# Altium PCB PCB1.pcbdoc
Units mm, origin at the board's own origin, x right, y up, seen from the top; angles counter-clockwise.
Board outline 74.17 x 55.75 mm, 2 copper layers (Top Layer, Bottom Layer); 37 components, 49 nets, 196 pads, 123 vias.
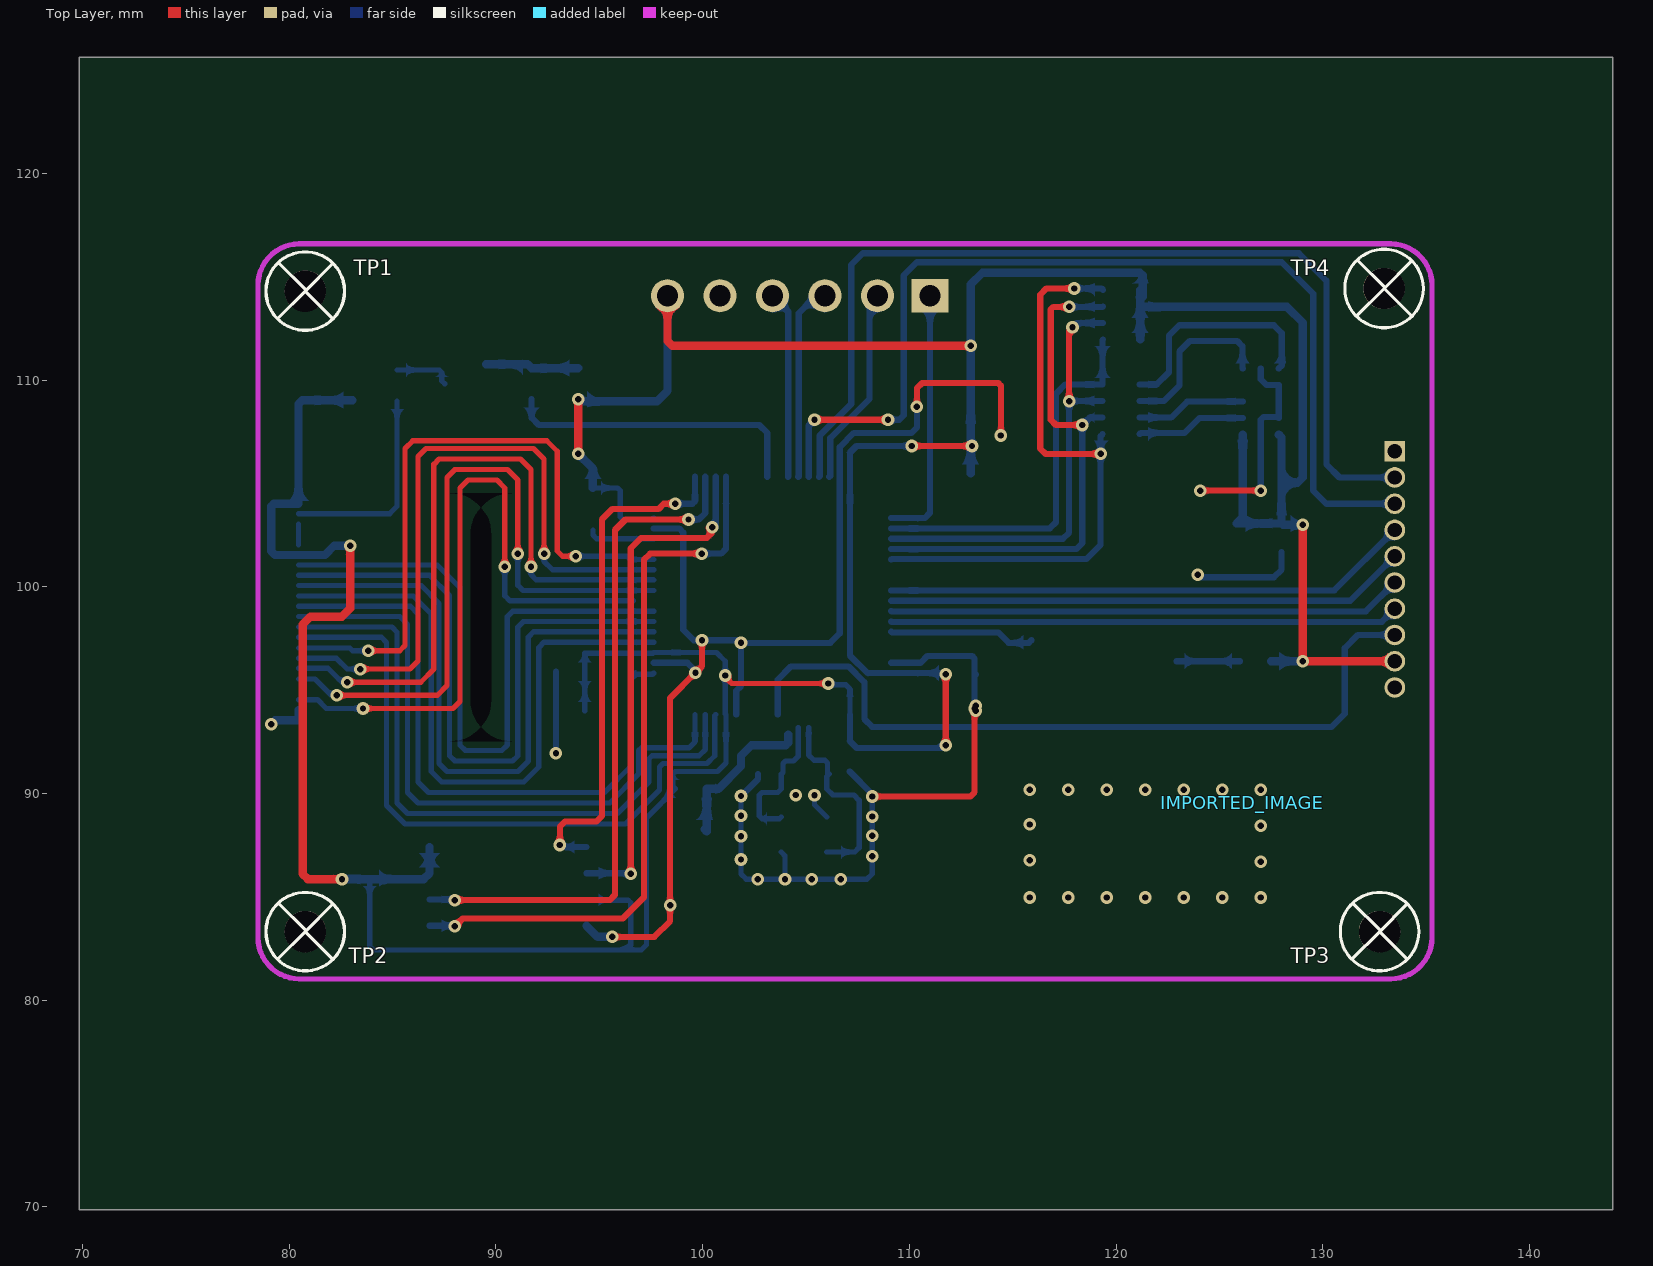
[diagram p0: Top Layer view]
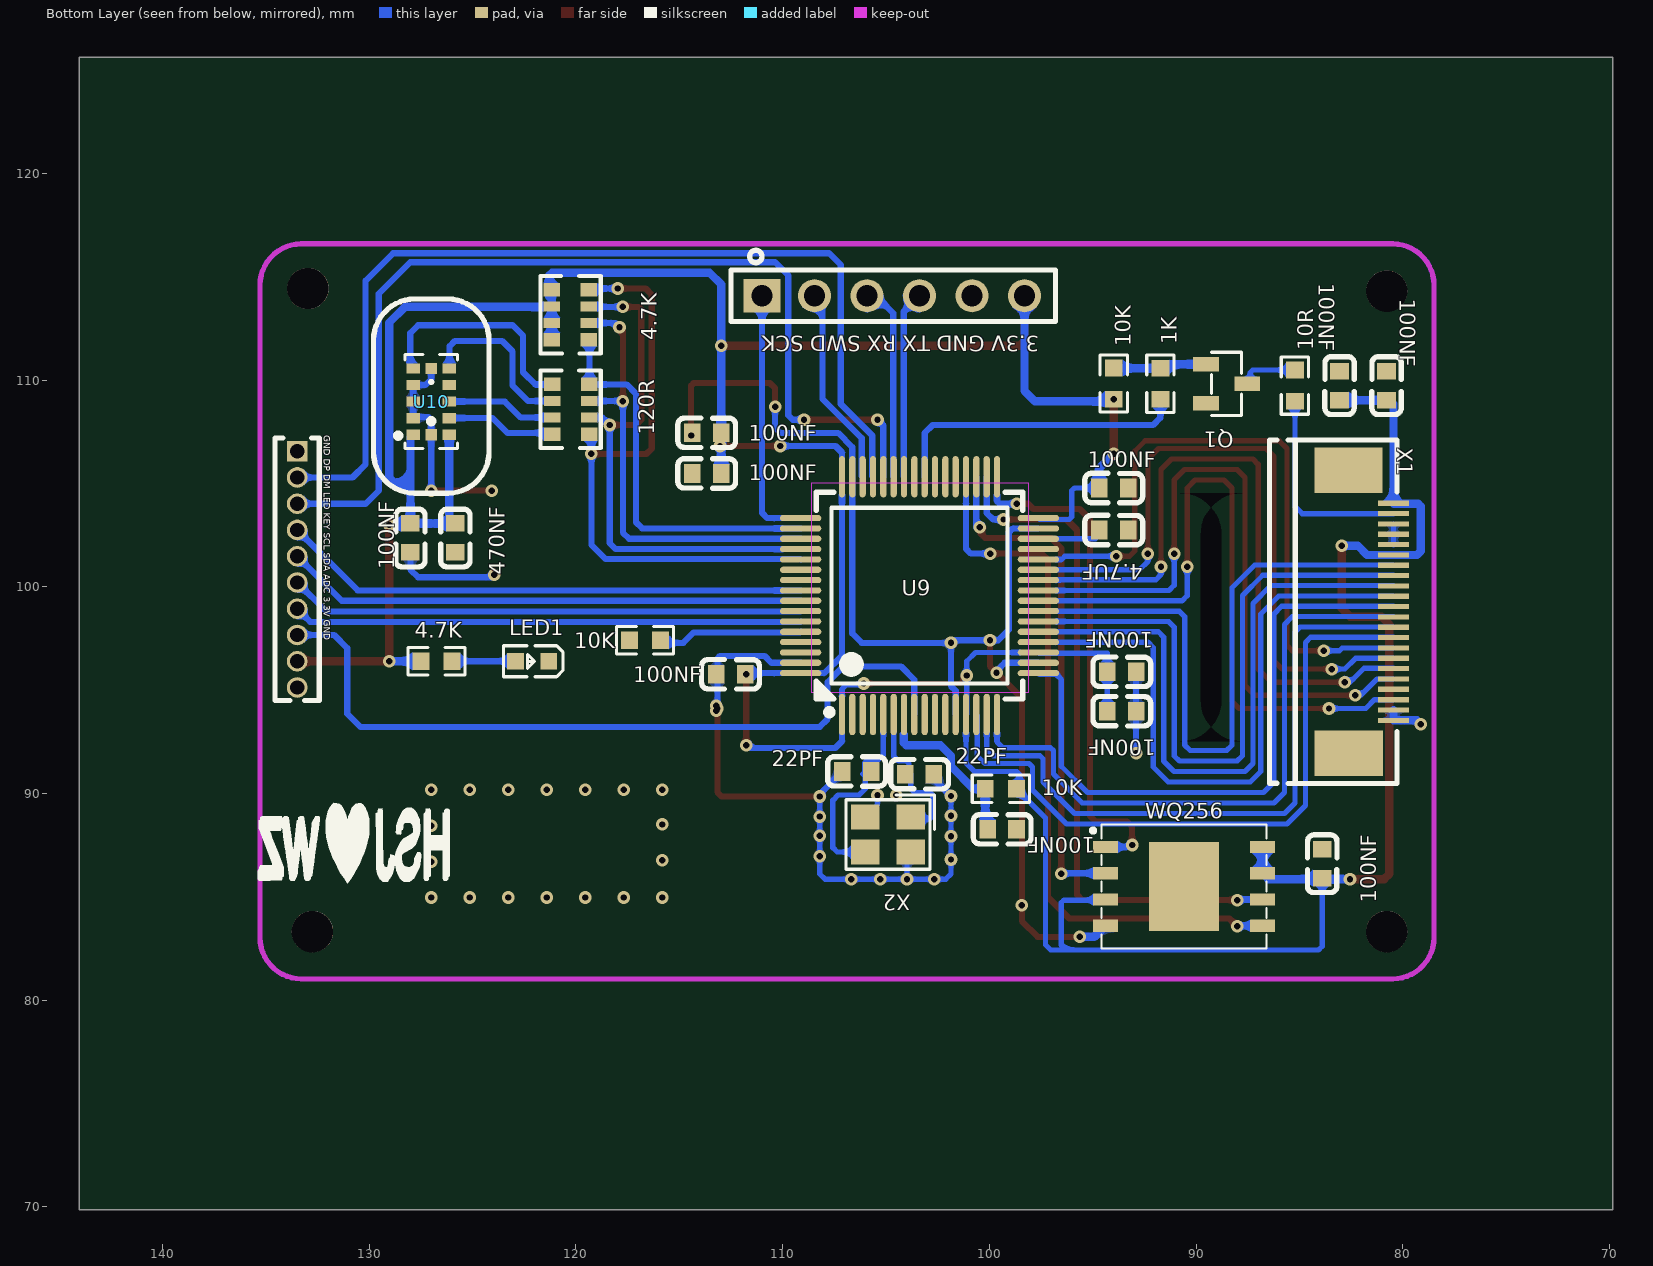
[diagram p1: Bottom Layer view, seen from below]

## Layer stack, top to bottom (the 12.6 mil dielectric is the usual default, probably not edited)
Top Layer: signal copper (thickness not stored)
Dielectric: dielectric 0.32, FR-4, Dk 4.8
Bottom Layer: signal copper (thickness not stored)

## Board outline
144.018,69.85 69.85,69.85 69.85,125.603 144.018,125.603
cut-out: 90.773,104.521 87.773,104.521 cw(c87.773,102.521) 89.773,102.521 89.773,94.521 cw(c87.773,94.521) 87.773,92.521 90.773,92.521 cw(c90.773,94.521) 88.773,94.521 88.773,102.521 cw(c90.773,102.521)

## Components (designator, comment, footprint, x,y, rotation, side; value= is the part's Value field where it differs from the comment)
1K "Res_0603" R0603 91.723,109.818 r90 bottom
"3.3V GND TX RX SWD SCK" "HDR-F_2.54_1x6P" HDR-TH_6P-P2.54-V-F 104.648,114.076 r180 bottom
4.7K "Res_0603" R0603 126.746,96.393 r180 bottom
4.7K "4D03WGJ0103T5E" RES-ARRAY-SMD_0603-8P-L3.2-W1.6-BL 120.269,113.157 r90 top
4.7UF "CAP_0603" C0603 93.988,102.743 r0 bottom
10K "Res_0603" R0603 99.441,90.223 r0 bottom
10K "Res_0603" R0603 116.659,97.409 r0 bottom
10K "Res_0603" R0603 93.98,109.829 r90 bottom
10R "Res_0603" R0603 85.217,109.731 r90 bottom
22PF "CAP_0603" C0603 106.412,91.059 r180 bottom
22PF "CAP_0603" C0603 103.378,90.932 r0 bottom
100NF "CAP_0603" C0603 83.892,86.605 r90 bottom
100NF "CAP_0603" C0603 93.988,104.775 r0 bottom
100NF "CAP_0603" C0603 93.599,95.885 r0 bottom
100NF "CAP_0603" C0603 112.514,95.758 r180 bottom
100NF "CAP_0603" C0603 113.665,105.475 r180 bottom
100NF "CAP_0603" C0603 113.665,107.442 r180 bottom
100NF "CAP_0603" C0603 93.599,93.98 r0 bottom
100NF "CAP_0603" C0603 99.385,88.265 r0 bottom
100NF "CAP_0603" C0603 83.058,109.723 r270 bottom
100NF "CAP_0603" C0603 80.782,109.723 r270 bottom
100NF "CAP_0603" C0603 128.007,102.362 r90 bottom
120R "4D03WGJ0103T5E" RES-ARRAY-SMD_0603-8P-L3.2-W1.6-BL 120.249,108.585 r270 top
470NF "CAP_0603" C0603 125.83,102.362 r90 bottom
"GND DP DM LED KEY SCL SDA ADC 3.3V GND" "KH-1.27PH180-1X10P-L7.2" HDR-TH_10P-P1.27-V-M 133.486,100.838 r270 bottom
IMPORTED_IMAGE "IMPORTED_IMAGE" IMPORTED_IMAGE 126.111,89.535 r0 top
LED1 "LED_0603-R" LED_0603 122.174,96.39 r0 bottom
Q1 "SS8050_C2150" SOT-23-3_L2.9-W1.3-P1.90-LS2.4-BR 88.519,109.815 r0 bottom
TP1 "M2螺丝" M2螺丝 80.772,114.3 r0 top
TP2 "M2螺丝" M2螺丝 80.772,83.312 r0 top
TP3 "M2螺丝" M2螺丝 132.75,83.312 r0 top
TP4 "M2螺丝" M2螺丝 132.969,114.427 r0 top
U9 "STM32F446RET6" LQFP-64_L10.0-W10.0-P0.50-LS12.0-BL 103.378,99.568 r180 bottom
U10 "VL53L0CXV0DH/1" OPTO-SMD_12P_VL53L0CXV0DH-1 127,108.957 r270 bottom
WQ256 "W25Q256JVEIQ" WSON-8_L6.0-W8.0-P1.27-BL-EP 90.583,85.5 r270 bottom
X1 "AFC07-S22ECA-00" FPC-SMD_AFC07-S22ECA-00 81.534,98.784 r270 bottom
X2 "3225-8.00-12-10-10/A" CRYSTAL-SMD_4P-L3.2-W2.5-BL 104.902,88.011 r0 bottom

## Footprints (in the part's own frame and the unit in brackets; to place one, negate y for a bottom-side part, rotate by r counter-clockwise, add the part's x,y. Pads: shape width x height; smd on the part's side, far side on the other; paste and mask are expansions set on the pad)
C0603 [mm]
  rect 0.8x0.9 smd paste+0 mask+0.051: 1(-0.7,0) 2(0.7,0)
  silkscreen extent -1.41,-0.71 1.39,0.72
CRYSTAL-SMD_4P-L3.2-W2.5-BL [mm]
  rect 1.4x1.2 smd mask+0.051: 1(-1.1,-0.85) 2(1.1,-0.85) 3(1.1,0.85) 4(-1.1,0.85)
  silkscreen extent -2.26,-1.91 2.03,1.68
FPC-SMD_AFC07-S22ECA-00 [mm]
  rect 0.25x1.5 smd mask+0.051: 1(-5.25,1.085) 2(-4.75,1.085) 3(-4.25,1.085) 4(-3.75,1.085) 5(-3.25,1.085) 6(-2.75,1.085) 7(-2.25,1.085) 8(-1.75,1.085) 9(-1.25,1.085) 10(-0.75,1.085) 11(-0.25,1.085) 12(0.25,1.085) 13(0.75,1.085) 14(1.25,1.085) 15(1.75,1.085) 16(2.25,1.085) 17(2.75,1.085) 18(3.25,1.085) 19(3.75,1.085) 20(4.25,1.085) 21(4.75,1.085) 22(5.25,1.085)
  rect 2.2x3.3 smd mask+0.051: 23(6.85,-1.078) 24(-6.851,-1.085)
  silkscreen extent -8.31,-4.91 8.3,1.26
HDR-TH_6P-P2.54-V-F [mm]
  rect 1.8x1.6 hole 1.02 mask+0.051: 1(-6.35,0)
  round 1.6 hole 1.02 mask+0.051: 2(-3.81,0) 3(-1.27,0) 4(1.27,0) 5(3.81,0) 6(6.35,0)
  silkscreen extent -7.85,-1.25 7.85,2.2
HDR-TH_10P-P1.27-V-M [mm]
  rect 1x1 hole 0.7 mask+0.051: 1(-5.715,0)
  round 1 hole 0.7 mask+0.051: 2(-4.445,0) 3(-3.175,0) 4(-1.905,0) 5(-0.635,0) 6(0.635,0) 7(1.905,0) 8(3.175,0) 9(4.445,0) 10(5.715,0)
  silkscreen extent -6.35,-1.07 6.35,1.07
IMPORTED_IMAGE [mm]
LED_0603 [mil]
  rect 31.5x31.5 smd paste+0 mask+2: 1(-33.5,-0.4) 2(29.5,-0.2)
  silkscreen extent -61,-30 53,30
LQFP-64_L10.0-W10.0-P0.50-LS12.0-BL [mm]
  oval 0.3x2 smd paste+0 mask+0.051: 1(-3.75,-5.75) 2(-3.25,-5.75) 3(-2.75,-5.75) 4(-2.25,-5.75) 5(-1.75,-5.75) 6(-1.25,-5.75) 7(-0.75,-5.75) 8(-0.25,-5.75) 9(0.25,-5.75) 10(0.75,-5.75) 11(1.25,-5.75) 12(1.75,-5.75) 13(2.25,-5.75) 14(2.75,-5.75) 15(3.25,-5.75) 16(3.75,-5.75) 33(3.75,5.75) 34(3.25,5.75) 35(2.75,5.75) 36(2.25,5.75) 37(1.75,5.75) 38(1.25,5.75) 39(0.75,5.75) 40(0.25,5.75) 41(-0.25,5.75) 42(-0.75,5.75) 43(-1.25,5.75) 44(-1.75,5.75) 45(-2.25,5.75) 46(-2.75,5.75) 47(-3.25,5.75) 48(-3.75,5.75)
  oval 2x0.3 smd paste+0 mask+0.051: 17(5.75,-3.75) 18(5.75,-3.25) 19(5.75,-2.75) 20(5.75,-2.25) 21(5.75,-1.75) 22(5.75,-1.25) 23(5.75,-0.75) 24(5.75,-0.25) 25(5.75,0.25) 26(5.75,0.75) 27(5.75,1.25) 28(5.75,1.75) 29(5.75,2.25) 30(5.75,2.75) 31(5.75,3.25) 32(5.75,3.75) 49(-5.75,3.75) 50(-5.75,3.25) 51(-5.75,2.75) 52(-5.75,2.25) 53(-5.75,1.75) 54(-5.75,1.25) 55(-5.75,0.75) 56(-5.75,0.25) 57(-5.75,-0.25) 58(-5.75,-0.75) 59(-5.75,-1.25) 60(-5.75,-1.75) 61(-5.75,-2.25) 62(-5.75,-2.75) 63(-5.75,-3.25) 64(-5.75,-3.75)
  silkscreen extent -5,-5.79 5,5
M2螺丝 [mm]
  round 2 hole 2 mask+0.051: 1(0,0)
  silkscreen extent -1.9,-1.9 1.9,1.9
OPTO-SMD_12P_VL53L0CXV0DH-1 [mm]
  rect 0.5x0.65 smd mask+0.051: 1(1.6,-0.875) 2(0.8,-0.875) 3(0,-0.875) 4(-0.8,-0.875) 5(-1.6,-0.875) 7(-1.6,0.875) 8(-0.8,0.875) 9(0,0.875) 10(0.8,0.875) 11(1.6,0.875)
  rect 0.55x0.55 smd mask+0.051: 6(-1.6,0) 12(1.6,0)
  silkscreen extent -2.28,-1.72 2.28,1.28
R0603 [mm]
  rect 0.806x0.864 smd paste-100 mask+0.051: 1(-0.753,0) 2(0.753,0)
  silkscreen extent -1.39,-0.66 1.39,0.66
RES-ARRAY-SMD_0603-8P-L3.2-W1.6-BL [mm]
  rect 0.65x0.8 smd far side mask+0.051: 1(-1.2,-0.9) 4(1.2,-0.9) 5(1.2,0.9) 8(-1.2,0.9)
  rect 0.5x0.8 smd far side mask+0.051: 2(-0.4,-0.9) 3(0.4,-0.9) 6(0.4,0.9) 7(-0.4,0.9)
SOT-23-3_L2.9-W1.3-P1.90-LS2.4-BR [mm]
  rect 1.25x0.7 smd mask+0.051: 1(1,-0.95) 2(1,0.95) 3(-1,0)
  silkscreen extent -0.73,-1.53 0.73,1.53
WSON-8_L6.0-W8.0-P1.27-BL-EP [mm]
  rect 0.6x1.2 smd paste+0 mask+0.051: 1(-1.905,-3.8) 2(-0.635,-3.8) 3(0.635,-3.8) 4(1.905,-3.8) 5(1.905,3.8) 6(0.635,3.8) 7(-0.635,3.8) 8(-1.905,3.8)
  rect 4.3x3.4 smd paste+0 mask+0.051: 9(0,0)
  silkscreen extent -3,-4.5 3,4

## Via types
v1: diameter 0.61, hole 0.305, Top Layer to Bottom Layer, 123 vias

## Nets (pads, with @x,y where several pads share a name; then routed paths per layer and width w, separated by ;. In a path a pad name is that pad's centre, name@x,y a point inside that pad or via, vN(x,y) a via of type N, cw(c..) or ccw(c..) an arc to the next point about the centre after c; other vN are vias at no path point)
$1N8240: 4.7UF.2 U9.30 | length 3.3
  Bottom Layer w0.254: 4.7UF.2 94.688,102.499 94.869,102.318 U9.30
$1N11180: 1K.2 10K.2@93.98,110.583 Q1.1 | length 4.5
  Bottom Layer w0.4: Q1.1 91.529,110.765 1K.2 93.969,110.571 10K.2@93.98,110.583
$1N11181: 10R.2 Q1.3 | length 2.8
  Bottom Layer w0.254: 10R.2 87.255,110.484 87.376,110.363 87.376,109.958 Q1.3
$1N11182: 10R.1 X1.2 | length 10
  Bottom Layer w0.254: X1.2 84.857,103.534 85.217,103.894 10R.1
$1N14668: 120R.5 U10.10 | length 5.3
  Bottom Layer w0.3: 120R.5 121.206,107.442 123.317,107.442 124.032,108.157 U10.10
$1N14670: 120R.6 U10.9 | length 5.3
  Bottom Layer w0.3: 120R.6 122.663,108.185 123.435,108.957 U10.9
$1N14672: 120R.7 U10.7 | length 8.3
  Bottom Layer w0.3: 120R.7 122.32,108.985 123.063,109.728 123.063,111.379 123.571,111.887 125.857,111.887 126.111,111.633 126.111,110.571 U10.7
$1N14674: 120R.8 U10.5 | length 11
  Bottom Layer w0.3: 120R.8 121.977,109.785 122.555,110.363 122.555,112.141 123.063,112.649 127.635,112.649 128.016,112.268 128.016,110.698 U10.5
$1N17660: 4.7K.2@125.993,96.393 LED1.2 | length 3.1
  Bottom Layer w0.3: LED1.2 125.99,96.396 4.7K.2@125.993,96.393
+3.3V: 4.7K.1 4.7K.2@121.169,112.757 4.7K.3 4.7K.4 10K.1@93.98,109.076 10K.1@98.688,90.223 100NF.1@83.892,85.904 100NF.2@80.782,109.023 100NF.2@83.058,109.023 100NF.2@94.299,93.98 100NF.2@94.299,95.885 100NF.2@94.688,104.775 100NF.2@111.814,95.758 100NF.2@112.965,105.475 100NF.2@112.965,107.442 100NF.2@128.007,103.062 470NF.2 "3.3V GND TX RX SWD SCK.6" "GND DP DM LED KEY SCL SDA ADC 3.3V GND.9" U9.1 U9.13 U9.19 U9.32 U9.48 U9.64 U10.1 U10.11 WQ256.3 WQ256.7 WQ256.8 X1.1 X1.6 | length 224.1
  Top Layer w0.254: v1@101.092,95.631 101.405,95.318 v1(106.069,95.318)
  Top Layer w0.3: v1(110.109,106.807) v1(113.03,106.807) ; v1(111.76,92.329) v1(111.76,95.758)
  Top Layer w0.4: v1(82.55,85.852) 80.899,85.852 80.645,86.106 80.645,98.171 81.026,98.552 82.55,98.552 82.943,98.945 v1(82.943,101.981) ; v1(93.98,106.426) v1(93.98,109.076) ; v1(98.298,114.076) 98.298,111.887 98.534,111.651 v1(112.965,111.651) ; v1(129.032,102.997) v1(129.032,96.393) v1(133.486,96.393)
  Bottom Layer w0.254: 100NF.1@83.892,85.904 83.892,85.852 83.892,82.605 84.074,82.423 96.266,82.423 ; 100NF.2@94.299,93.98 94.299,95.885 94.299,96.774 97.584,96.774 U9.19 100.667,96.818 101.092,96.393 v1(101.092,95.703) 101.092,93.854 U9.13 101.128,91.476 100.711,91.059 98.679,91.059 98.552,90.932 98.552,90.359 98.688,90.223 97.282,88.817 97.282,82.677 97.028,82.423 96.266,82.423 ; WQ256.3 94.411,84.836 96.393,84.836 96.52,84.709 96.52,82.677 96.266,82.423 ; 100NF.2@94.688,104.775 95.885,104.775 96.012,104.648 96.012,103.378 96.139,103.251 97.561,103.251 U9.32 ; v1@106.045,95.25 106.934,95.25 107.128,95.056 U9.1
  Bottom Layer w0.3: U9.1 107.128,92.516 107.442,92.202 111.633,92.202 v1(111.76,92.329) ; v1(110.109,106.807) 107.442,106.807 107.128,106.493 U9.48 107.128,96.668 107.978,95.818 U9.64 111.754,95.818 100NF.2@111.814,95.758
  Bottom Layer w0.4: v1(82.55,85.852) 83.892,85.852 86.5,85.852 WQ256.7 WQ256.8 ; v1(82.943,101.981) 82.169,101.981 81.722,101.534 X1.6 79.314,101.534 79.121,101.727 79.121,103.886 79.248,104.013 80.428,104.013 X1.1 80.449,108.839 80.633,109.023 80.782,109.023 100NF.2@83.058,109.023 ; v1(93.98,106.426) 94.688,105.718 100NF.2@94.688,104.775 ; v1(93.98,109.076) 94.09,108.966 97.79,108.966 98.298,109.474 v1(98.298,114.076) ; 100NF.2@112.965,105.475 112.965,107.442 v1(112.965,111.651) 112.965,114.616 113.538,115.189 121.158,115.189 121.285,115.062 121.285,114.034 121.169,113.918 ; 4.7K.1@121.169,111.957 121.169,112.757 4.7K.3 ; 4.7K.4 121.169,113.918 ; U10.11 126.125,103.357 470NF.2 100NF.2@128.007,103.062 ; 4.7K.1@127.499,96.393 v1(129.032,96.393) ; U10.1 128.007,107.225 128.007,105.029 ; v1(129.032,102.997) 128.073,102.997 100NF.2@128.007,103.062 ; 4.7K.3 121.188,113.538 128.27,113.538 129.032,112.776 129.032,105.283 128.778,105.029 128.007,105.029 ; 4.7K.3 121.169,113.918 ; 100NF.2@128.007,103.062 128.007,105.029
  other v1: 82.55,85.852 111.76,92.329 106.069,95.318 129.032,96.393 129.032,96.393 82.943,101.981 82.943,101.981 129.032,102.997 93.98,106.426 110.109,106.807 110.109,106.807
A0: U9.14 X1.14 | length 32.5
  Bottom Layer w0.254: X1.14@80.449,97.552 84.455,97.552 84.709,97.298 84.709,89.408 85.598,88.519 96.266,88.519 97.917,90.17 97.917,91.275 98.082,91.44 100.203,91.44 100.584,91.821 100.584,93.774 U9.14
A1: U9.15 X1.13 | length 31.9
  Bottom Layer w0.254: X1.13@80.449,98.052 84.963,98.052 85.217,97.798 85.217,89.535 85.725,89.027 95.885,89.027 97.409,90.551 97.409,91.678 97.552,91.821 99.822,91.821 100.128,92.127 U9.15
A2: U9.16 X1.12 | length 30.9
  Bottom Layer w0.254: X1.12@80.449,98.552 85.344,98.552 85.725,98.171 85.725,90.043 86.233,89.535 95.504,89.535 96.901,90.932 96.901,92.067 97.036,92.202 99.339,92.202 99.628,92.491 U9.16
A3: U9.17 X1.11 | length 30.5
  Bottom Layer w0.254: X1.11@80.449,99.052 85.86,99.052 86.233,98.679 86.233,90.551 86.741,90.043 95.25,90.043 96.52,91.313 96.52,95.504 96.774,95.758 97.568,95.758 U9.17
A4: U9.20 X1.10 | length 31.6
  Bottom Layer w0.254: X1.10@80.449,99.552 85.995,99.552 86.868,98.679 86.868,91.059 87.376,90.551 91.34,90.551 92.075,91.286 92.075,97.064 92.329,97.318 U9.20
A5: U9.21 X1.9 | length 31.8
  Bottom Layer w0.254: X1.9@80.449,100.052 86.384,100.052 87.249,99.187 87.249,91.44 87.63,91.059 91.059,91.059 91.567,91.567 91.567,97.564 91.821,97.818 U9.21
A6: U9.22 X1.8 | length 31.9
  Bottom Layer w0.254: X1.8@80.449,100.552 86.773,100.552 87.757,99.568 87.757,91.821 88.011,91.567 90.805,91.567 91.059,91.821 91.059,98.044 91.313,98.298 U9.22
A7: U9.23 X1.7 | length 31.8
  Bottom Layer w0.254: X1.7@80.449,101.052 87.162,101.052 88.265,99.949 88.265,92.329 88.519,92.075 90.278,92.075 90.551,92.348 90.551,98.552 90.805,98.806 97.616,98.806 U9.23
B0: U9.26 X1.17 | length 33.1
  Top Layer w0.254: v1(82.804,95.377) 86.36,95.377 86.995,96.012 86.995,105.918 87.249,106.172 91.186,106.172 91.694,105.664 v1(91.694,100.965)
  Bottom Layer w0.254: X1.17@80.449,96.052 81.875,96.052 82.55,95.377 v1(82.804,95.377) ; v1(91.694,100.965) 91.694,100.584 91.948,100.33 97.616,100.33 U9.26
  other v1: 91.694,100.965
B1: U9.27 X1.16 | length 32.9
  Top Layer w0.254: v1(83.439,96.012) 85.842,96.012 86.233,96.403 86.233,106.299 86.614,106.68 91.821,106.68 92.329,106.172 v1(92.329,101.6)
  Bottom Layer w0.254: X1.16 82.282,96.534 82.804,96.012 v1(83.439,96.012) ; v1(92.329,101.6) 92.329,101.219 92.73,100.818 U9.27
  other v1: 83.439,96.012 92.329,101.6
B2: U9.28 X1.15 | length 32.2
  Top Layer w0.254: v1(83.82,96.901) 85.344,96.901 85.598,97.155 85.598,106.68 85.979,107.061 92.456,107.061 92.964,106.553 92.964,101.727 93.218,101.473 v1(93.853,101.473)
  Bottom Layer w0.254: X1.15 82.925,97.034 83.058,96.901 v1(83.82,96.901) ; v1(93.853,101.473) 96.346,101.473 96.501,101.318 U9.28
  other v1: 83.82,96.901 93.853,101.473
BAT_ADC: "GND DP DM LED KEY SCL SDA ADC 3.3V GND.8" U9.8 | length 37.8
  Bottom Layer w0.3: U9.8 103.628,95.5 104.267,96.139 107.061,96.139 107.823,95.377 107.823,93.599 108.204,93.218 130.429,93.218 131.064,93.853 131.064,97.028 131.699,97.663 133.486,97.663
BOOT0: 10K.1@115.905,97.409 U9.60 | length 7.1
  Bottom Layer w0.3: U9.60 109.156,97.79 114.3,97.79 114.808,97.282 115.778,97.282 10K.1@115.905,97.409
C4: U9.24 X1.20 | length 32.5
  Top Layer w0.254: v1(83.566,94.107) 87.923,94.107 88.265,94.449 88.265,104.775 88.646,105.156 90.043,105.156 90.424,104.775 v1(90.424,100.965)
  Bottom Layer w0.254: X1.20 81.361,94.534 81.788,94.107 v1(83.566,94.107) ; v1(90.424,100.965) 90.424,99.566 90.676,99.314 U9.24@96.647,99.314
  other v1: 90.424,100.965
C5: U9.25 X1.18 | length 33.3
  Top Layer w0.254: v1(82.296,94.742) 87.156,94.742 87.63,95.216 87.63,105.283 88.011,105.664 90.551,105.664 91.059,105.156 v1(91.059,101.6)
  Bottom Layer w0.254: X1.18 81.25,95.534 82.042,94.742 v1(82.296,94.742) ; v1(91.059,101.6) 91.059,100.072 91.313,99.818 U9.25
  other v1: 82.296,94.742 91.059,101.6
C9: 1K.1 U9.40 | length 14.7
  Bottom Layer w0.3: 1K.1 91.723,108.175 92.075,107.823 102.743,107.823 103.124,107.442 103.124,105.322 U9.40
GND: 4.7UF.1 10K.2@117.412,97.409 22PF.1 100NF.1@80.782,110.423 100NF.1@83.058,110.423 100NF.1@92.899,93.98 100NF.1@92.899,95.885 100NF.1@93.288,104.775 100NF.1@98.685,88.265 100NF.1@113.214,95.758 100NF.1@114.365,105.475 100NF.1@114.365,107.442 100NF.1@128.007,101.662 100NF.2@83.892,87.305 470NF.1 "3.3V GND TX RX SWD SCK.5" "GND DP DM LED KEY SCL SDA ADC 3.3V GND.1" "GND DP DM LED KEY SCL SDA ADC 3.3V GND.10" LED1.1 Q1.2 U9.12 U9.18 U9.31 U9.47 U9.63 U10.2 U10.3 U10.4 U10.6 U10.12 WQ256.4 X1.3 X1.4 X1.5 X1.21 X1.22 X2.2 X2.4 | length 118.5
  Top Layer w0.3: v1(95.631,83.058) 97.663,83.058 98.425,83.82 v1(98.425,84.582) 98.425,94.615 v1(99.649,95.839) 99.968,96.158 v1(99.968,97.409) ; v1(108.204,89.848) 112.943,89.848 113.157,90.062 v1(113.157,94.107) ; v1(110.363,108.712) 110.363,109.601 110.617,109.855 114.3,109.855 114.427,109.728 v1(114.427,107.315) ; v1(124.079,104.648) v1(127,104.648)
  Bottom Layer w0.254: X1.5 X1.4 X1.3 ; v1(101.854,89.873) v1(101.854,88.915) v1(101.854,87.932) v1(101.854,86.802) 101.854,86.106 102.108,85.852 v1(102.658,85.852) v1(103.985,85.852) ; X2.4 103.985,86.978 v1(103.985,85.852) ; v1(105.41,89.916) 105.41,89.453 X2.2 ; v1(108.204,89.848) v1(108.204,88.878) v1(108.204,87.944) v1(108.204,86.961) 108.204,86.106 107.95,85.852 v1(106.68,85.852) v1(105.283,85.852) v1(103.985,85.852)
  Bottom Layer w0.3: v1(92.899,91.948) 92.899,93.98 100NF.1@92.899,95.885 ; U9.18 99.262,96.318 v1@99.695,95.885 ; U9.31 98.858,102.818 99.06,102.616 99.06,97.917 99.568,97.409 v1(99.968,97.409) 101.727,97.409 v1(101.854,97.282) ; U9.12 101.628,94.968 101.854,95.194 v1(101.854,97.282) ; v1(101.854,89.873) 102.678,90.697 22PF.1@102.678,90.932 ; 22PF.1@107.112,91.059 108.204,89.967 v1(108.204,89.848) ; U9.63 110.542,96.318 110.871,96.647 113.03,96.647 113.157,96.52 113.157,95.815 113.214,95.758 113.157,95.701 v1(113.157,94.107) ; v1(110.363,108.712) 110.363,107.696 110.109,107.442 107.315,107.442 106.628,106.755 U9.47 106.628,97.738 106.172,97.282 v1(101.854,97.282) ; v1(123.952,100.584) 124.079,100.457 127.635,100.457 128.007,100.829 100NF.1@128.007,101.662 ; v1(127,104.648) U10.12 127,108.077 127.127,108.204 127.828,108.204 U10.2 U10.3 U10.4 127.283,109.757 127.281,109.755 127,110.036 U10.6
  Bottom Layer w0.4: v1(79.121,93.345) 79.31,93.534 X1.22 X1.21 ; WQ256.4 94.919,83.058 v1(95.631,83.058)
  other v1: 115.824,84.963 117.687,84.963 119.549,84.963 121.412,84.963 123.275,84.963 125.137,84.963 127,84.963 127,86.699 115.824,86.762 127,88.434 115.824,88.498 104.502,89.918 115.824,90.17 117.687,90.17 119.549,90.17 121.412,90.17 123.275,90.17 125.137,90.17 127,90.17 113.214,93.998 113.214,94.234 127,104.648 110.363,108.712
IIC_SCL: "GND DP DM LED KEY SCL SDA ADC 3.3V GND.6" U9.58 | length 24.9
  Bottom Layer w0.3: U9.58 109.14,98.806 132.089,98.806 133.486,100.203
IIC_SDA: "GND DP DM LED KEY SCL SDA ADC 3.3V GND.7" U9.59 | length 24.6
  Bottom Layer w0.3: U9.59 109.148,98.298 132.851,98.298 133.486,98.933
KEY_GPIO: "GND DP DM LED KEY SCL SDA ADC 3.3V GND.5" U9.57 | length 25.3
  Bottom Layer w0.3: U9.57 131.331,99.318 133.486,101.473
LED_GPIO: "GND DP DM LED KEY SCL SDA ADC 3.3V GND.4" U9.56 | length 25.6
  Bottom Layer w0.3: U9.56 130.561,99.818 133.486,102.743
NRST: 10K.2@100.194,90.223 100NF.2@100.085,88.265 U9.7 | length 7.8
  Bottom Layer w0.4: 100NF.2@100.085,88.265 100.194,88.156 100.194,90.223 100.764,90.223 101.854,91.313 101.854,91.821 102.362,92.329 104.013,92.329 104.14,92.456 U9.7@104.14,92.85
OSC_IN: 22PF.2@105.712,91.059 U9.5 X2.3 | length 9.5
  Bottom Layer w0.254: U9.5@105.128,93.183 105.128,91.855 105.382,91.601 105.918,91.601 106.045,91.474 22PF.2@106.045,90.932 ; X2.3 107.354,87.161 107.569,87.376 107.569,89.662 107.315,89.916 106.299,89.916 106.002,90.213 106.002,90.814 106.12,90.932
OSC_OUT: 22PF.2@104.078,90.932 U9.6 X2.1 | length 6.9
  Bottom Layer w0.254: X2.1 103.714,88.773 102.87,88.773 102.743,88.9 102.743,89.916 102.87,90.043 103.632,90.043 103.802,90.213 103.802,90.923 103.886,91.007 103.886,91.44 104.013,91.567 104.394,91.567 104.628,91.801 U9.6@104.628,93.183
RX: "3.3V GND TX RX SWD SCK.3" U9.43 | length 9.5
  Bottom Layer w0.3: U9.43 104.648,105.338 104.648,113.23 105.494,114.076 105.918,114.076
SCK: "3.3V GND TX RX SWD SCK.1" U9.49 | length 12.5
  Bottom Layer w0.3: U9.49 110.743,103.318 110.998,103.573 110.998,114.076
SPI2_CS: U9.33 WQ256.1 | length 24.6
  Top Layer w0.3: v1(93.091,87.503) 93.091,88.392 93.345,88.646 94.869,88.646 95.123,88.9 95.123,103.251 95.631,103.759 97.864,103.759 98.118,104.013 v1(98.679,104.013)
  Bottom Layer w0.3: v1@93.345,87.405 WQ256.1 ; v1(98.679,104.013) 99.505,104.013 99.628,104.136 U9.33
  other v1: 93.091,87.503 98.679,104.013
SPI2_MISO: U9.35 WQ256.2 | length 25
  Top Layer w0.3: v1(96.52,86.106) 96.52,101.854 97.028,102.362 100.203,102.362 100.457,102.616 v1(100.457,102.87)
  Bottom Layer w0.3: WQ256.2 96.491,86.135 v1(96.52,86.106) ; v1(100.457,102.87) 100.628,102.87 U9.35
  other v1: 96.52,86.106 100.457,102.87
SPI2_MOSI: U9.36 WQ256.5 | length 35
  Top Layer w0.3: v1(88.011,83.566) 88.392,83.947 96.139,83.947 97.155,84.963 97.155,101.3 97.455,101.6 v1(99.949,101.6)
  Bottom Layer w0.3: WQ256.5 87.982,83.595 v1(88.011,83.566) ; v1(99.949,101.6) 100.891,101.6 101.128,101.837 U9.36
  other v1: 99.949,101.6
SPI2_SCK: U9.34 WQ256.6 | length 33.2
  Top Layer w0.3: v1(88.011,84.836) 95.504,84.836 95.758,85.09 95.758,102.743 96.266,103.251 v1(99.314,103.251)
  Bottom Layer w0.3: WQ256.6 87.982,84.865 v1(88.011,84.836) ; v1(99.314,103.251) 99.816,103.251 100.128,103.563 U9.34
  other v1: 88.011,84.836
SWD: "3.3V GND TX RX SWD SCK.2" U9.46 | length 9.7
  Bottom Layer w0.3: U9.46 106.172,105.362 106.172,107.188 108.077,109.093 108.077,113.695 108.458,114.076
TX: "3.3V GND TX RX SWD SCK.4" U9.42 | length 9.1
  Bottom Layer w0.3: 103.378,114.076 104.14,113.314 104.14,105.33 U9.42
USB_FS_DM: "GND DP DM LED KEY SCL SDA ADC 3.3V GND.3" U9.44 | length 48.5
  Top Layer w0.3: v1(105.41,108.077) v1(108.966,108.077)
  Bottom Layer w0.3: U9.44 105.128,107.795 v1(105.41,108.077) ; v1(108.966,108.077) 109.511,108.077 109.728,108.294 109.728,115.062 110.363,115.697 128.016,115.697 129.54,114.173 129.54,104.648 130.175,104.013 133.486,104.013
  other v1: 105.41,108.077 108.966,108.077
USB_FS_DP: "GND DP DM LED KEY SCL SDA ADC 3.3V GND.2" U9.45 | length 47.1
  Bottom Layer w0.3: U9.45 105.664,105.354 105.664,107.315 107.188,108.839 107.188,115.57 107.754,116.136 128.847,116.136 130.175,114.808 130.175,105.918 130.81,105.283 133.486,105.283
VL_INT: 4.7K.7 120R.2 U9.51 | length 21.7
  Top Layer w0.3: v1(117.729,108.966) v1@117.729,112.395
  Bottom Layer w0.3: U9.51 117.429,102.318 117.729,102.618 v1(117.729,108.966) 117.748,108.985 120R.2 ; v1(117.893,112.559) 118.091,112.757 4.7K.7
  other v1: 117.729,108.966 117.893,112.559
VL_SCL: 4.7K.5 120R.4 U9.53 | length 29.5
  Top Layer w0.3: v1(117.983,114.427) 116.632,114.427 116.332,114.127 116.332,106.68 116.586,106.426 v1(119.253,106.426)
  Bottom Layer w0.3: U9.53 109.156,101.346 118.572,101.346 119.253,102.027 v1(119.253,106.426) 119.253,107.289 120R.4 ; v1(117.983,114.427) 119.299,114.427 4.7K.5
  other v1: 119.253,106.426 117.983,114.427
VL_SDA: 4.7K.6 120R.3 U9.52 | length 25.8
  Top Layer w0.3: v1(117.729,113.538) 116.967,113.538 116.84,113.411 116.84,108.077 117.094,107.823 v1(118.364,107.823)
  Bottom Layer w0.3: U9.52 118.074,101.818 118.364,102.108 v1(118.364,107.823) 118.726,108.185 120R.3 ; v1(117.729,113.538) 119.35,113.538 4.7K.6
  other v1: 118.364,107.823 117.729,113.538
VL_XSH: 4.7K.8 120R.1 U9.50 | length 18.9
  Bottom Layer w0.3: U9.50 116.794,102.818 117.094,103.118 117.094,109.328 117.551,109.785 120R.1 119.349,111.937 4.7K.8
"": TP1.1 TP2.1 TP3.1 TP4.1 U9.2 U9.3 U9.4 U9.9 U9.10 U9.11 U9.29 U9.37 U9.38 U9.39 U9.41 U9.54 U9.55 U9.61 U9.62 U10.8 WQ256.9 X1.19 X1.23 X1.24

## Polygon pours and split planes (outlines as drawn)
GND on Top Layer (hatched 45Degree grid 30 track 10, remove dead copper, pour order 0): 77.724,78.994 136.906,78.994 136.906,117.729 77.724,117.729
GND on Bottom Layer (hatched 45Degree grid 30 track 10, remove dead copper, pour order 1): 76.2,76.2 137.668,76.2 137.668,119.253 76.2,119.253

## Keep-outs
Bottom Layer:
  region net "": 98.118,94.869 108.585,94.869 108.585,105.029 98.118,105.029
Board Outline Layer:
  lines w0.254 net "": 78.486,83.026 ccw(c80.486,83.026) 80.486,81.026 133.286,81.026 ccw(c133.286,83.026) 135.286,83.026 135.286,114.586 ccw(c133.286,114.586) 133.286,116.586 80.486,116.586 ccw(c80.486,114.586) 78.486,114.586 78.486,83.026

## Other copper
Top Layer:
  drawing of 80 lines, arcs and shapes, not listed
Bottom Layer:
  drawing of 202 lines, arcs and shapes, not listed

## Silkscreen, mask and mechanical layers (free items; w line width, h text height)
Bottom Silkscreen Layer:
  lines w0.254 net "": 124.206,106.521 ccw(c126.206,106.521) 126.206,104.521 127.794,104.521 ccw(c127.794,106.521) 129.794,106.521 129.794,111.919 ccw(c127.794,111.919) 127.794,113.919 126.206,113.919 ccw(c126.206,111.919) 124.206,111.919 124.206,106.521
Mechanical Layer:
  lines w0.025 net "": 87.773,92.521 ccw(c87.773,94.521) 89.773,94.521 89.773,102.521 ccw(c87.773,102.521) 87.773,104.521 90.773,104.521 ccw(c90.773,102.521) 88.773,102.521 88.773,94.521 ccw(c90.773,94.521) 90.773,92.521 87.773,92.521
